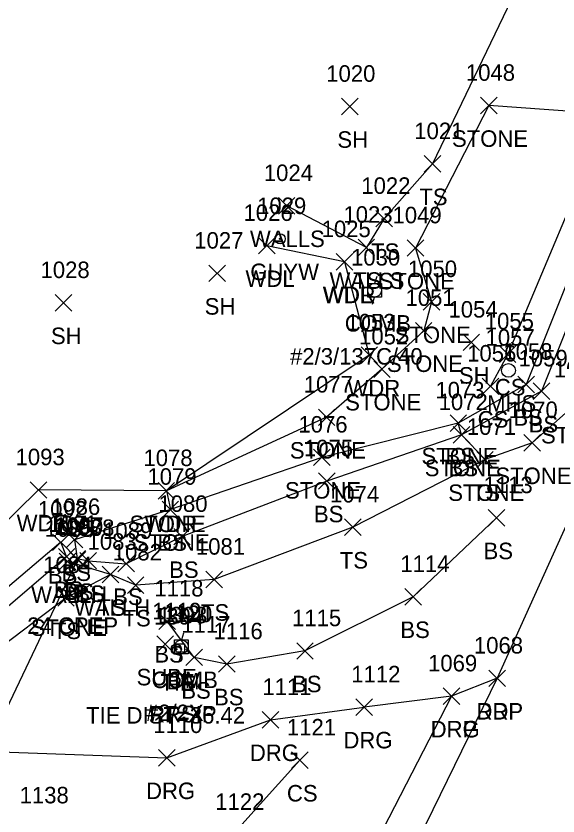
# Model space of a CAD drawing. Extents: x 1599840 to 1601211, y 518904 to 521989.
# Drawn here: x 1600815.1 to 1600880.7, y 521353.5 to 521450.4 of the extents above; entities that cross this region are included whole.
import ezdxf

# ---------------------------------------------------------------- set-up
doc = ezdxf.new("R2010")
doc.units = 0
for name, color, linetype in [('C_A', 7, 'Continuous'), ('C_C', 7, 'Continuous'), ('C_I', 7, 'Continuous'), ('CBP', 7, 'Continuous'), ('CPBM', 7, 'Continuous'), ('D_A', 7, 'Continuous'), ('D_C', 7, 'Continuous'), ('D_I', 7, 'Continuous'), ('D_TIC', 7, 'Continuous'), ('DCP', 7, 'Continuous'), ('DHW', 7, 'Continuous'), ('L_A', 7, 'Continuous'), ('L_I', 7, 'Continuous'), ('L_TIC', 7, 'Continuous'), ('LASF', 7, 'Continuous'), ('LAWA', 7, 'Continuous'), ('LELB', 7, 'Continuous'), ('LWS', 7, 'Continuous'), ('P_A', 7, 'Continuous'), ('P_I', 7, 'Continuous'), ('P_TIC', 7, 'Continuous'), ('PET', 7, 'Continuous'), ('R_A', 7, 'Continuous'), ('R_I', 7, 'Continuous'), ('R_TIC', 7, 'Continuous'), ('RDG', 7, 'Continuous'), ('RDP', 7, 'Continuous'), ('U_A', 7, 'Continuous'), ('U_C', 7, 'Continuous'), ('U_I', 7, 'Continuous'), ('U_TIC', 7, 'Continuous'), ('UP', 7, 'Continuous'), ('UPGW', 7, 'Continuous'), ('USMH', 7, 'Continuous')]:
    doc.layers.add(name, color=color, linetype=linetype)

msp = doc.modelspace()

# ---------------------------------------------------------------- linework, layer by layer
at = {"layer": 'CBP'}
for radius in [0.625, 0.0833]:
    msp.add_circle((1600834.493, 521373.668), radius, dxfattribs=at)
at = {"layer": 'CPBM'}
for p, q in [((1600834.488, 521373.314), (1600834.488, 521374.314)), ((1600834.488, 521374.314), (1600835.488, 521374.314)), ((1600834.991, 521373.814), (1600834.991, 521373.814)), ((1600834.991, 521373.814), (1600834.991, 521373.814)), ((1600835.488, 521374.314), (1600835.488, 521373.314)), ((1600835.488, 521373.314), (1600834.488, 521373.314))]:
    msp.add_line(p, q, dxfattribs=at)
at = {"layer": 'D_TIC'}
for points in [[(1600820.333, 521383.294), (1600822.333, 521385.294)], [(1600822.333, 521383.294), (1600820.333, 521385.294)], [(1600821.553, 521383.532), (1600823.553, 521385.532)], [(1600823.553, 521383.532), (1600821.553, 521385.532)], [(1600825.528, 521381.724), (1600827.528, 521383.724)], [(1600827.528, 521381.724), (1600825.528, 521383.724)]]:
    msp.add_lwpolyline(points, dxfattribs=at)
at = {"layer": 'DCP'}
msp.add_lwpolyline([(1600822.553, 521384.532), (1600796.227, 521329.266)], dxfattribs=at)
at = {"layer": 'DHW'}
msp.add_lwpolyline([(1600826.528, 521382.724), (1600821.333, 521384.294)], dxfattribs=at)
at = {"layer": 'L_TIC'}
for points in [[(1600854.517, 521438.414), (1600856.517, 521440.414)], [(1600856.517, 521438.414), (1600854.517, 521440.414)], [(1600871.337, 521438.531), (1600873.337, 521440.531)], [(1600873.337, 521438.531), (1600871.337, 521440.531)], [(1600864.519, 521431.468), (1600866.519, 521433.468)], [(1600866.519, 521431.468), (1600864.519, 521433.468)], [(1600846.87, 521426.391), (1600848.87, 521428.391)], [(1600848.87, 521426.391), (1600846.87, 521428.391)], [(1600858.674, 521424.835), (1600860.674, 521426.835)], [(1600860.674, 521424.835), (1600858.674, 521426.835)], [(1600844.467, 521421.555), (1600846.467, 521423.555)], [(1600846.467, 521421.555), (1600844.467, 521423.555)], [(1600856.51, 521421.336), (1600858.51, 521423.336)], [(1600858.51, 521421.336), (1600856.51, 521423.336)], [(1600856.51, 521421.336), (1600858.51, 521423.336)], [(1600858.51, 521421.336), (1600856.51, 521423.336)], [(1600862.462, 521421.268), (1600864.462, 521423.268)], [(1600864.462, 521421.268), (1600862.462, 521423.268)], [(1600853.869, 521419.592), (1600855.869, 521421.592)], [(1600855.869, 521419.592), (1600853.869, 521421.592)], [(1600853.869, 521419.592), (1600855.869, 521421.592)], [(1600855.869, 521419.592), (1600853.869, 521421.592)], [(1600838.448, 521418.202), (1600840.448, 521420.202)], [(1600840.448, 521418.202), (1600838.448, 521420.202)], [(1600819.835, 521414.636), (1600821.835, 521416.636)], [(1600821.835, 521414.636), (1600819.835, 521416.636)], [(1600864.406, 521414.757), (1600866.406, 521416.757)], [(1600866.406, 521414.757), (1600864.406, 521416.757)], [(1600863.458, 521411.26), (1600865.458, 521413.26)], [(1600865.458, 521411.26), (1600863.458, 521413.26)], [(1600869.23, 521409.847), (1600871.23, 521411.847)], [(1600871.23, 521409.847), (1600869.23, 521411.847)], [(1600873.623, 521408.419), (1600875.623, 521410.419)], [(1600875.623, 521408.419), (1600873.623, 521410.419)], [(1600856.866, 521408.294), (1600858.866, 521410.294)], [(1600858.866, 521408.294), (1600856.866, 521410.294)], [(1600858.405, 521406.599), (1600860.405, 521408.599)], [(1600860.405, 521406.599), (1600858.405, 521408.599)], [(1600871.546, 521404.524), (1600873.546, 521406.524)], [(1600873.546, 521404.524), (1600871.546, 521406.524)], [(1600875.873, 521404.745), (1600877.873, 521406.745)], [(1600877.873, 521404.745), (1600875.873, 521406.745)], [(1600877.723, 521403.941), (1600879.723, 521405.941)], [(1600879.723, 521403.941), (1600877.723, 521405.941)], [(1600851.703, 521400.768), (1600853.703, 521402.768)], [(1600853.703, 521400.768), (1600851.703, 521402.768)], [(1600867.644, 521400.061), (1600869.644, 521402.061)], [(1600869.644, 521400.061), (1600867.644, 521402.061)], [(1600867.644, 521400.061), (1600869.644, 521402.061)], [(1600869.644, 521400.061), (1600867.644, 521402.061)], [(1600868.037, 521398.635), (1600870.037, 521400.635)], [(1600870.037, 521398.635), (1600868.037, 521400.635)], [(1600868.037, 521398.635), (1600870.037, 521400.635)], [(1600870.037, 521398.635), (1600868.037, 521400.635)], [(1600876.594, 521397.681), (1600878.594, 521399.681)], [(1600878.594, 521397.681), (1600876.594, 521399.681)], [(1600851.114, 521395.92), (1600853.114, 521397.92)], [(1600853.114, 521395.92), (1600851.114, 521397.92)], [(1600870.885, 521395.639), (1600872.885, 521397.639)], [(1600872.885, 521395.639), (1600870.885, 521397.639)], [(1600870.885, 521395.639), (1600872.885, 521397.639)], [(1600872.885, 521395.639), (1600870.885, 521397.639)], [(1600851.727, 521393.053), (1600853.727, 521395.053)], [(1600853.727, 521393.053), (1600851.727, 521395.053)], [(1600816.811, 521391.965), (1600818.811, 521393.965)], [(1600818.811, 521391.965), (1600816.811, 521393.965)], [(1600832.295, 521391.861), (1600834.295, 521393.861)], [(1600834.295, 521391.861), (1600832.295, 521393.861)], [(1600832.295, 521391.861), (1600834.295, 521393.861)], [(1600834.295, 521391.861), (1600832.295, 521393.861)], [(1600832.786, 521389.599), (1600834.786, 521391.599)], [(1600834.786, 521389.599), (1600832.786, 521391.599)], [(1600832.786, 521389.599), (1600834.786, 521391.599)], [(1600834.786, 521389.599), (1600832.786, 521391.599)], [(1600832.786, 521389.599), (1600834.786, 521391.599)], [(1600834.786, 521389.599), (1600832.786, 521391.599)], [(1600872.264, 521388.583), (1600874.264, 521390.583)], [(1600874.264, 521388.583), (1600872.264, 521390.583)], [(1600854.883, 521387.451), (1600856.883, 521389.451)], [(1600856.883, 521387.451), (1600854.883, 521389.451)], [(1600834.193, 521386.311), (1600836.193, 521388.311)], [(1600836.193, 521386.311), (1600834.193, 521388.311)], [(1600819.512, 521385.628), (1600821.512, 521387.628)], [(1600821.512, 521385.628), (1600819.512, 521387.628)], [(1600821.166, 521385.945), (1600823.166, 521387.945)], [(1600823.166, 521385.945), (1600821.166, 521387.945)], [(1600820.218, 521383.888), (1600822.218, 521385.888)], [(1600822.218, 521383.888), (1600820.218, 521385.888)], [(1600820.218, 521383.888), (1600822.218, 521385.888)], [(1600822.218, 521383.888), (1600820.218, 521385.888)], [(1600821.504, 521383.648), (1600823.504, 521385.648)], [(1600823.504, 521383.648), (1600821.504, 521385.648)], [(1600822.833, 521383.4), (1600824.833, 521385.4)], [(1600824.833, 521383.4), (1600822.833, 521385.4)], [(1600827.421, 521383.037), (1600829.421, 521385.037)], [(1600829.421, 521383.037), (1600827.421, 521385.037)], [(1600827.421, 521383.037), (1600829.421, 521385.037)], [(1600829.421, 521383.037), (1600827.421, 521385.037)], [(1600825.528, 521381.724), (1600827.528, 521383.724)], [(1600827.528, 521381.724), (1600825.528, 521383.724)], [(1600828.586, 521380.436), (1600830.586, 521382.436)], [(1600830.586, 521380.436), (1600828.586, 521382.436)], [(1600838.079, 521381.129), (1600840.079, 521383.129)], [(1600840.079, 521381.129), (1600838.079, 521383.129)], [(1600820.146, 521378.907), (1600822.146, 521380.907)], [(1600822.146, 521378.907), (1600820.146, 521380.907)], [(1600862.187, 521379.033), (1600864.187, 521381.033)], [(1600864.187, 521379.033), (1600862.187, 521381.033)], [(1600832.404, 521376.063), (1600834.404, 521378.063)], [(1600834.404, 521376.063), (1600832.404, 521378.063)], [(1600835.669, 521371.686), (1600837.669, 521373.686)], [(1600837.669, 521371.686), (1600835.669, 521373.686)], [(1600849.077, 521372.468), (1600851.077, 521374.468)], [(1600851.077, 521372.468), (1600849.077, 521374.468)], [(1600839.63, 521370.882), (1600841.63, 521372.882)], [(1600841.63, 521370.882), (1600839.63, 521372.882)], [(1600848.454, 521359.23), (1600850.454, 521361.23)], [(1600850.454, 521359.23), (1600848.454, 521361.23)]]:
    msp.add_lwpolyline(points, dxfattribs=at)
at = {"layer": 'LASF'}
for points in [[(1600911.546, 521511.932), (1600900.224, 521479.947), (1600889.738, 521445.235), (1600886.885, 521438.481), (1600872.337, 521439.531), (1600863.462, 521422.268), (1600865.406, 521415.757), (1600864.458, 521412.26), (1600859.405, 521407.599), (1600852.703, 521401.768), (1600833.295, 521392.861), (1600833.786, 521390.599)], [(1600919.139, 521509.382), (1600909.758, 521476.008), (1600898.654, 521442.034), (1600883.119, 521403.602), (1600877.594, 521398.681), (1600871.885, 521396.639), (1600869.037, 521399.635), (1600868.644, 521401.061), (1600852.114, 521396.92), (1600833.786, 521390.599)]]:
    msp.add_lwpolyline(points, dxfattribs=at)
at = {"layer": 'LAWA'}
for points in [[(1600854.869, 521420.592), (1600845.467, 521422.555)], [(1600854.869, 521420.592), (1600857.866, 521409.294), (1600833.295, 521392.861), (1600817.811, 521392.965), (1600807.213, 521382.554), (1600788.481, 521372.639), (1600784.029, 521369.008)]]:
    msp.add_lwpolyline(points, dxfattribs=at)
at = {"layer": 'LELB'}
for points in [[(1600904.447, 521515.194), (1600887.343, 521478.495), (1600876.571, 521455.523), (1600865.519, 521432.468), (1600859.674, 521425.835), (1600857.51, 521422.336)], [(1600913.3, 521511.459), (1600903.304, 521478.92), (1600892.372, 521444.434), (1600876.873, 521405.745), (1600868.644, 521401.061)], [(1600915.473, 521510.949), (1600905.575, 521477.831), (1600894.081, 521443.303), (1600878.723, 521404.941), (1600869.037, 521399.635), (1600852.727, 521394.053), (1600835.193, 521387.311), (1600828.421, 521384.037)], [(1600886.885, 521438.481), (1600874.623, 521409.419), (1600872.546, 521405.524)], [(1600871.885, 521396.639), (1600855.883, 521388.451), (1600839.079, 521382.129), (1600829.586, 521381.436), (1600826.528, 521382.724), (1600821.146, 521379.907), (1600811.956, 521372.971), (1600790.906, 521366.24), (1600768.259, 521360.253)], [(1600833.786, 521390.599), (1600822.166, 521386.945), (1600822.504, 521384.648), (1600823.833, 521384.4), (1600828.421, 521384.037)], [(1600873.264, 521389.583), (1600863.187, 521380.033), (1600850.077, 521373.468), (1600840.63, 521371.882), (1600836.669, 521372.686), (1600833.404, 521377.063)], [(1600821.218, 521384.888), (1600820.512, 521386.628), (1600810.802, 521378.413), (1600789.658, 521368.932), (1600784.13, 521367.774), (1600766.803, 521364.192)], [(1600821.218, 521384.888), (1600811.311, 521376.459), (1600790.382, 521367.475), (1600768.259, 521360.253)], [(1600849.454, 521360.23), (1600841.344, 521351.215), (1600843.17, 521332.508)]]:
    msp.add_lwpolyline(points, dxfattribs=at)
at = {"layer": 'LWS'}
msp.add_lwpolyline([(1600857.51, 521422.336), (1600847.87, 521427.391)], dxfattribs=at)
at = {"layer": 'P_TIC'}
for points in [[(1600872.353, 521369.155), (1600874.353, 521371.155)], [(1600874.353, 521369.155), (1600872.353, 521371.155)]]:
    msp.add_lwpolyline(points, dxfattribs=at)
at = {"layer": 'PET'}
msp.add_lwpolyline([(1600925.829, 521507.518), (1600915.18, 521473.309), (1600903.262, 521440.284), (1600887.481, 521401.444), (1600873.353, 521370.155), (1600860.378, 521343.642), (1600847.931, 521319.686), (1600844.651, 521313.138), (1600836.724, 521299.896), (1600818.79, 521271.507), (1600793.687, 521233.92), (1600774.487, 521208.057), (1600757.089, 521185.54), (1600730.915, 521154.494)], dxfattribs=at)
at = {"layer": 'R_TIC'}
for points in [[(1600872.353, 521369.155), (1600874.353, 521371.155)], [(1600874.353, 521369.155), (1600872.353, 521371.155)], [(1600866.812, 521366.992), (1600868.812, 521368.992)], [(1600868.812, 521366.992), (1600866.812, 521368.992)], [(1600866.812, 521366.992), (1600868.812, 521368.992)], [(1600868.812, 521366.992), (1600866.812, 521368.992)], [(1600856.247, 521365.665), (1600858.247, 521367.665)], [(1600858.247, 521365.665), (1600856.247, 521367.665)], [(1600856.247, 521365.665), (1600858.247, 521367.665)], [(1600858.247, 521365.665), (1600856.247, 521367.665)], [(1600844.915, 521364.131), (1600846.915, 521366.131)], [(1600846.915, 521364.131), (1600844.915, 521366.131)], [(1600832.35, 521359.525), (1600834.35, 521361.525)], [(1600834.35, 521359.525), (1600832.35, 521361.525)]]:
    msp.add_lwpolyline(points, dxfattribs=at)
at = {"layer": 'RDG'}
for points in [[(1600867.812, 521367.992), (1600857.247, 521366.665)], [(1600767.555, 521356.23), (1600789.875, 521358.718), (1600808.695, 521361.402), (1600833.35, 521360.525), (1600845.915, 521365.131), (1600857.247, 521366.665)]]:
    msp.add_lwpolyline(points, dxfattribs=at)
at = {"layer": 'RDP'}
msp.add_lwpolyline([(1600873.353, 521370.155), (1600867.812, 521367.992), (1600856.102, 521345.272), (1600846.401, 521325.716), (1600847.931, 521319.686)], dxfattribs=at)
at = {"layer": 'U_TIC'}
for points in [[(1600832.157, 521373.299), (1600834.157, 521375.299)], [(1600834.157, 521373.299), (1600832.157, 521375.299)]]:
    msp.add_lwpolyline(points, dxfattribs=at)
at = {"layer": 'UP'}
for p, q in [((1600858.764, 521418.819), (1600858.514, 521417.985)), ((1600857.681, 521416.319), (1600857.681, 521417.985)), ((1600857.681, 521417.985), (1600859.348, 521417.985)), ((1600858.514, 521417.152), (1600858.514, 521417.152)), ((1600859.348, 521417.985), (1600859.348, 521416.319)), ((1600859.348, 521416.319), (1600857.681, 521416.319)), ((1600858.264, 521415.485), (1600858.514, 521416.319)), ((1600835.371, 521375.633), (1600835.121, 521374.8)), ((1600834.288, 521373.133), (1600834.288, 521374.8)), ((1600834.288, 521374.8), (1600835.954, 521374.8)), ((1600835.954, 521374.8), (1600835.954, 521373.133)), ((1600835.121, 521373.967), (1600835.121, 521373.967)), ((1600835.954, 521373.133), (1600834.288, 521373.133)), ((1600834.871, 521372.3), (1600835.121, 521373.133))]:
    msp.add_line(p, q, dxfattribs=at)
for centre in [(1600858.514, 521417.152), (1600835.121, 521373.967)]:
    msp.add_circle(centre, 0.833, dxfattribs=at)
at = {"layer": 'UPGW'}
for radius in [0.625, 0.0833]:
    msp.add_circle((1600847.066, 521423.388), radius, dxfattribs=at)
at = {"layer": 'USMH'}
for p, q in [((1600874.718, 521407.448), (1600874.718, 521407.448)), ((1600875.552, 521407.448), (1600875.552, 521407.448))]:
    msp.add_line(p, q, dxfattribs=at)
msp.add_circle((1600874.718, 521407.448), 0.833, dxfattribs=at)

# ---------------------------------------------------------------- texts
at = {"layer": 'C_A'}
for s, p in [('TIE', (1600832.572, 521368.668)), ('BM', (1600833.305, 521368.814))]:
    msp.add_text(s, height=2, dxfattribs=at).set_placement(p)
at = {"layer": 'C_C'}
for s, p in [('RRSIP', (1600831.203, 521364.814)), ('TIE DIST=36.42', (1600823.58, 521364.668))]:
    msp.add_text(s, height=2, dxfattribs=at).set_placement(p)
at = {"layer": 'C_I'}
for s, p in [('1394', (1600831.8, 521376.668)), ('1393', (1600832.298, 521376.814))]:
    msp.add_text(s, height=2, dxfattribs=at).set_placement(p)
at = {"layer": 'D_A'}
for s, p in [('WALLH', (1600816.923, 521379.294)), ('P', (1600821.931, 521379.532)), ('WALLH', (1600822.119, 521377.724))]:
    msp.add_text(s, height=2, dxfattribs=at).set_placement(p)
at = {"layer": 'D_C'}
for s, p in [('24 CPEP', (1600816.451, 521375.532)), ('STONE', (1600816.876, 521375.294))]:
    msp.add_text(s, height=2, dxfattribs=at).set_placement(p)
at = {"layer": 'D_I'}
for s, p in [('1085', (1600818.561, 521387.294)), ('1090', (1600819.695, 521387.532)), ('1083', (1600823.756, 521385.724))]:
    msp.add_text(s, height=2, dxfattribs=at).set_placement(p)
at = {"layer": 'L_A'}
for s, p in [('STONE', (1600867.881, 521434.531)), ('SH', (1600854.005, 521434.414)), ('TS', (1600863.928, 521427.468)), ('WALLS', (1600843.413, 521422.391)), ('TS', (1600858.084, 521420.835)), ('WDL', (1600842.884, 521417.555)), ('WALLS', (1600853.053, 521417.336)), ('TS', (1600855.92, 521417.336)), ('STONE', (1600859.006, 521417.268)), ('WDR', (1600852.231, 521415.592)), ('WDL', (1600852.286, 521415.592)), ('SH', (1600837.937, 521414.202)), ('SH', (1600819.323, 521410.636)), ('STONE', (1600860.949, 521410.757)), ('STONE', (1600860.001, 521407.26)), ('SH', (1600868.718, 521405.847)), ('WDR', (1600855.229, 521404.294)), ('CS', (1600873.064, 521404.419)), ('STONE', (1600854.949, 521402.599)), ('BS', (1600875.314, 521400.745)), ('CS', (1600870.987, 521400.524)), ('BS', (1600877.164, 521399.941)), ('STONE', (1600878.662, 521398.602)), ('STONE', (1600848.247, 521396.768)), ('STONE', (1600864.187, 521396.061)), ('BS', (1600867.085, 521396.061)), ('STONE', (1600864.58, 521394.635)), ('BS', (1600867.478, 521394.635)), ('STONE', (1600873.138, 521393.681)), ('STONE', (1600847.658, 521391.92)), ('STONE', (1600867.429, 521391.639)), ('TS', (1600870.295, 521391.639)), ('BS', (1600851.168, 521389.053)), ('WDR', (1600815.174, 521387.965)), ('STONE', (1600828.839, 521387.861)), ('WDR', (1600830.658, 521387.861)), ('STONE', (1600829.33, 521385.599)), ('STONE', (1600829.33, 521385.599)), ('BS', (1600832.227, 521385.599)), ('BS', (1600871.705, 521384.583)), ('TS', (1600854.293, 521383.451)), ('BS', (1600833.634, 521382.311)), ('BS', (1600818.953, 521381.628)), ('BS', (1600820.607, 521381.945)), ('BS', (1600819.659, 521379.888)), ('BS', (1600819.659, 521379.888)), ('BS', (1600820.945, 521379.648)), ('BS', (1600822.274, 521379.4)), ('BS', (1600826.862, 521379.037)), ('BS', (1600826.862, 521379.037)), ('TS', (1600824.937, 521377.724)), ('TS', (1600827.995, 521376.436)), ('TS', (1600837.489, 521377.129)), ('TS', (1600819.556, 521374.907)), ('BS', (1600861.628, 521375.033)), ('BS', (1600831.844, 521372.063)), ('BS', (1600835.11, 521367.686)), ('BS', (1600848.518, 521368.468)), ('BS', (1600839.071, 521366.882)), ('CS', (1600847.895, 521355.23))]:
    msp.add_text(s, height=2, dxfattribs=at).set_placement(p)
at = {"layer": 'L_I'}
for s, p in [('1020', (1600852.658, 521442.414)), ('1048', (1600869.566, 521442.531)), ('1021', (1600863.314, 521435.468)), ('1024', (1600845.098, 521430.391)), ('1022', (1600856.903, 521428.835)), ('1026', (1600842.64, 521425.555)), ('1023', (1600854.739, 521425.336)), ('1023', (1600854.739, 521425.336)), ('1049', (1600860.683, 521425.268)), ('1025', (1600852.098, 521423.592)), ('1025', (1600852.098, 521423.592)), ('1027', (1600836.677, 521422.202)), ('1028', (1600818.063, 521418.636)), ('1050', (1600862.548, 521418.757)), ('1051', (1600862.253, 521415.26)), ('1054', (1600867.459, 521413.847)), ('1053', (1600855.095, 521412.294)), ('1055', (1600871.852, 521412.419)), ('1052', (1600856.634, 521410.599)), ('1056', (1600869.719, 521408.524)), ('1058', (1600874.101, 521408.745)), ('1059', (1600875.944, 521407.941)), ('1060', (1600880.213, 521406.602)), ('1077', (1600849.932, 521404.768)), ('1073', (1600865.872, 521404.061)), ('1073', (1600865.872, 521404.061)), ('1072', (1600866.265, 521402.635)), ('1072', (1600866.265, 521402.635)), ('1070', (1600874.736, 521401.681)), ('1076', (1600849.288, 521399.92)), ('1071', (1600869.681, 521399.639)), ('1071', (1600869.681, 521399.639)), ('1075', (1600849.955, 521397.053)), ('1093', (1600815.04, 521395.965)), ('1078', (1600830.524, 521395.861)), ('1078', (1600830.524, 521395.861)), ('1079', (1600831.007, 521393.599)), ('1079', (1600831.007, 521393.599)), ('1079', (1600831.007, 521393.599)), ('1113', (1600871.706, 521392.583)), ('1074', (1600853.112, 521391.451)), ('1086', (1600819.34, 521389.945)), ('1080', (1600832.335, 521390.311)), ('1092', (1600817.74, 521389.628)), ('1091', (1600819.014, 521387.888)), ('1091', (1600819.014, 521387.888)), ('1087', (1600819.733, 521387.648)), ('1088', (1600821.062, 521387.4)), ('1089', (1600825.641, 521387.037)), ('1089', (1600825.641, 521387.037)), ('1083', (1600823.756, 521385.724)), ('1081', (1600836.875, 521385.129)), ('1082', (1600826.814, 521384.436)), ('1084', (1600818.375, 521382.907)), ('1114', (1600861.628, 521383.033)), ('1118', (1600831.845, 521380.063)), ('1115', (1600848.518, 521376.468)), ('1117', (1600835.111, 521375.686)), ('1116', (1600839.016, 521374.882)), ('1121', (1600847.895, 521363.23)), ('1122', (1600839.218, 521354.215))]:
    msp.add_text(s, height=2, dxfattribs=at).set_placement(p)
at = {"layer": 'P_A'}
msp.add_text('RDP', height=2, dxfattribs=at).set_placement((1600870.842, 521365.155))
at = {"layer": 'P_I'}
msp.add_text('1068', height=2, dxfattribs=at).set_placement((1600870.535, 521373.155))
at = {"layer": 'R_A'}
for s, p in [('DRP', (1600870.842, 521365.155)), ('DRG', (1600865.3, 521362.992)), ('DRP', (1600865.3, 521362.992)), ('DRG', (1600854.735, 521361.665)), ('DRG', (1600854.735, 521361.665)), ('DRG', (1600843.403, 521360.131)), ('DRG', (1600830.838, 521355.525))]:
    msp.add_text(s, height=2, dxfattribs=at).set_placement(p)
at = {"layer": 'R_I'}
for s, p in [('1068', (1600870.535, 521373.155)), ('1069', (1600864.985, 521370.992)), ('1069', (1600864.985, 521370.992)), ('1112', (1600855.688, 521369.665)), ('1112', (1600855.688, 521369.665)), ('1111', (1600844.923, 521368.131)), ('1110', (1600831.705, 521363.525)), ('1138', (1600815.532, 521355.007))]:
    msp.add_text(s, height=2, dxfattribs=at).set_placement(p)
at = {"layer": 'U_A'}
for s, p in [('GUYW', (1600843.459, 521418.388)), ('COMB', (1600854.9, 521412.152)), ('MHS', (1600872.136, 521402.448)), ('SUBE', (1600829.693, 521369.299)), ('COMB', (1600831.507, 521368.967))]:
    msp.add_text(s, height=2, dxfattribs=at).set_placement(p)
at = {"layer": 'U_C'}
for s, p in [('#2/3/137C/40', (1600848.271, 521408.152)), ('#2/2X', (1600830.822, 521364.967))]:
    msp.add_text(s, height=2, dxfattribs=at).set_placement(p)
at = {"layer": 'U_I'}
for s, p in [('1029', (1600844.286, 521426.388)), ('1030', (1600855.656, 521420.152)), ('1057', (1600871.947, 521410.448)), ('1119', (1600831.591, 521377.299)), ('1120', (1600832.909, 521376.967))]:
    msp.add_text(s, height=2, dxfattribs=at).set_placement(p)

doc.saveas('drawing.dxf')
